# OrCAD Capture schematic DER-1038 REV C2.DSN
size D
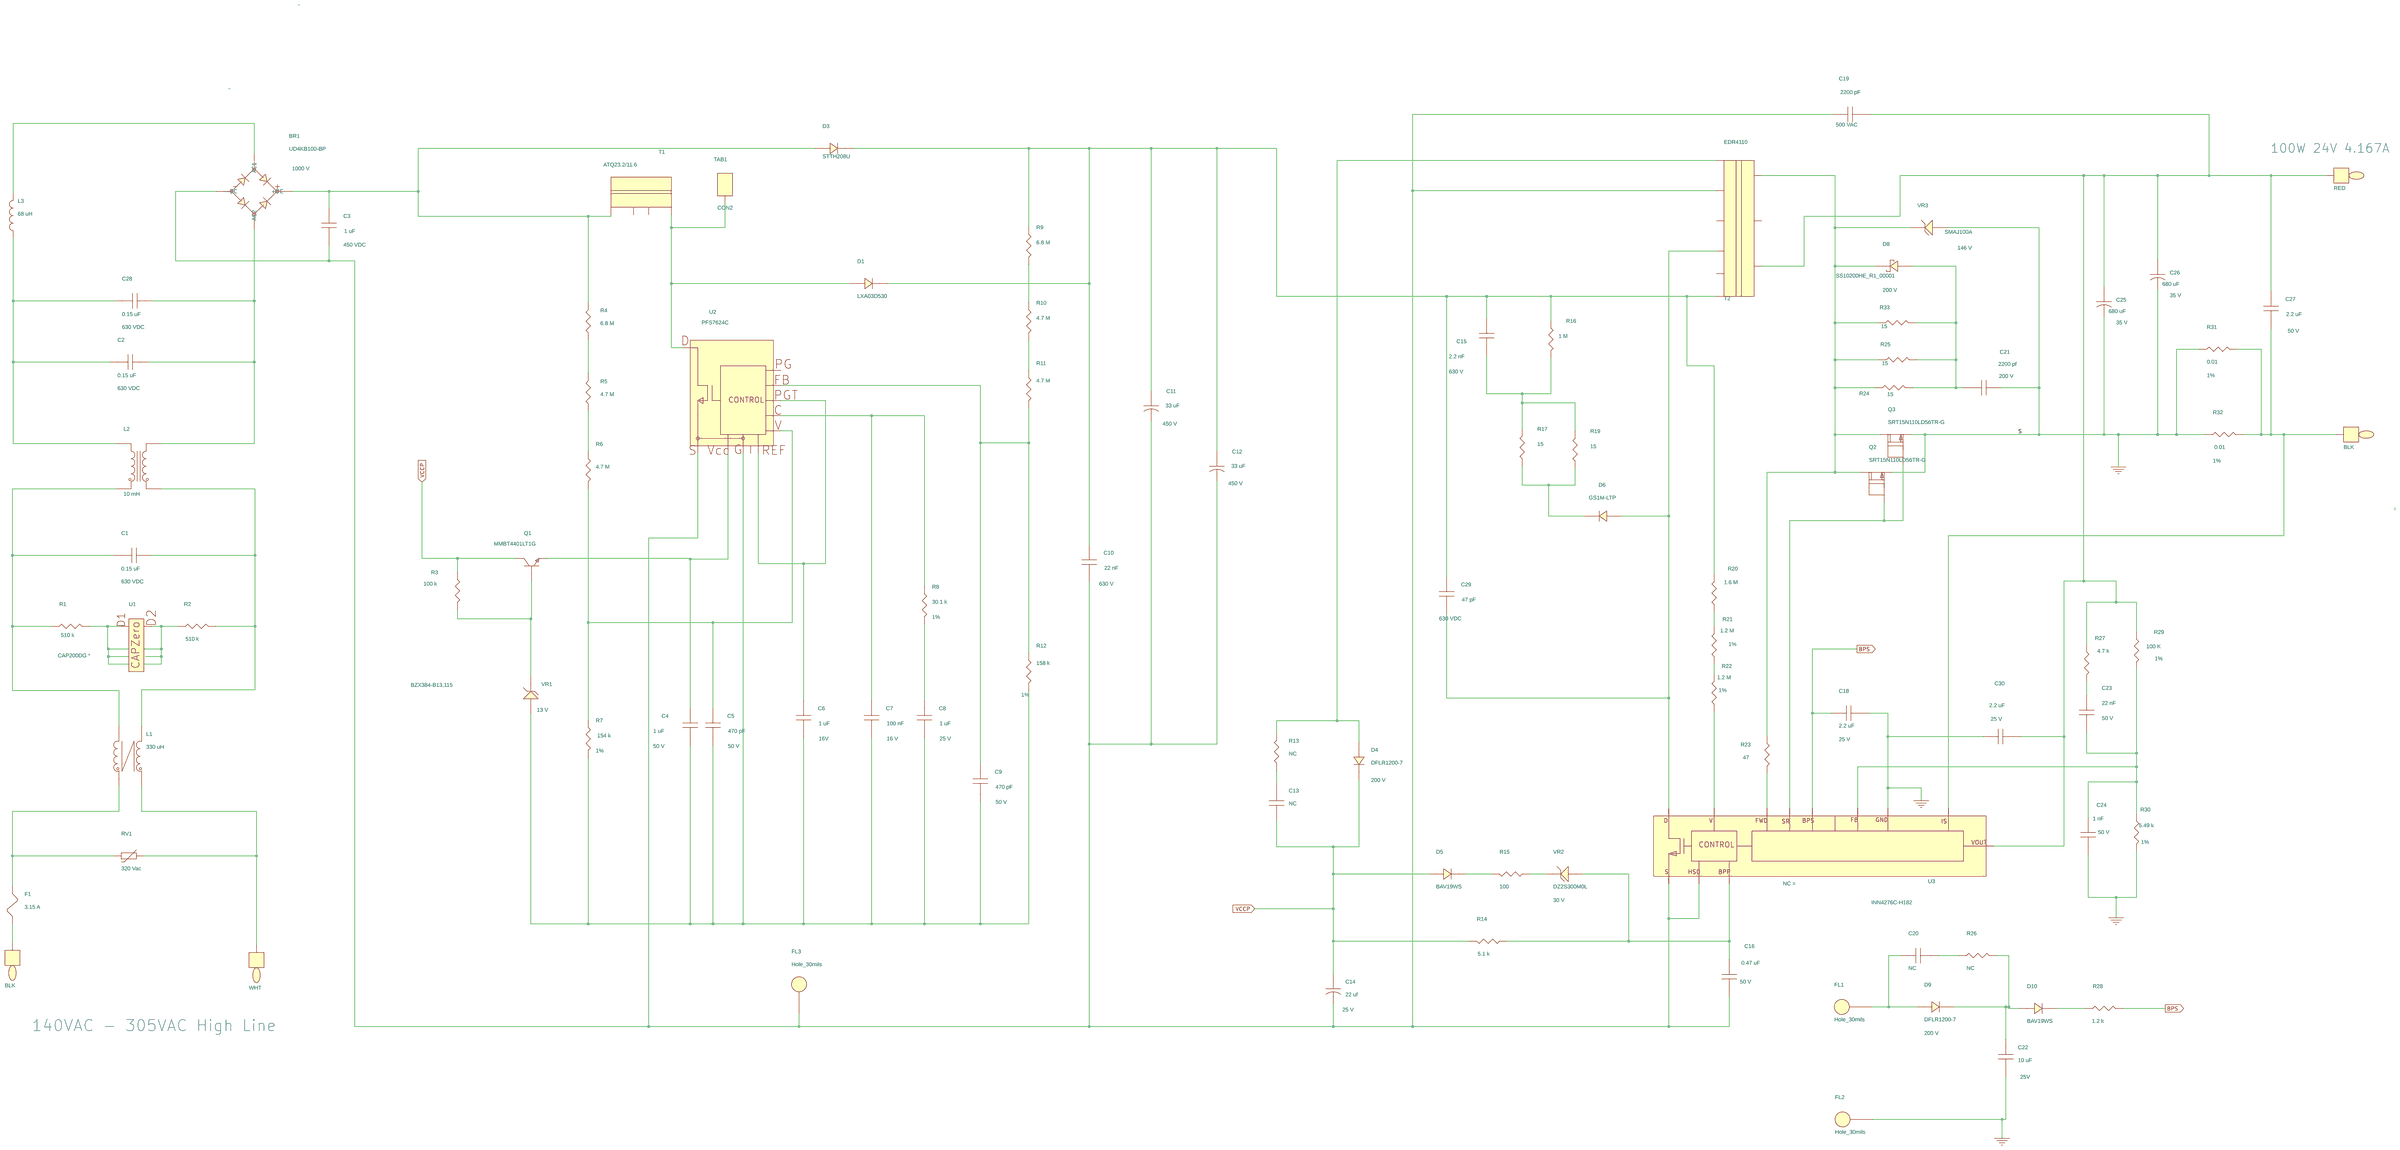
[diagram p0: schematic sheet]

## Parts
BR1  UD4KB100-BP  [pidaxbridgeD3K]
C1  0.15 uF  [pinpxcaprad13x6mm040]
C2  0.15 uF  [pinpxcaprad13x6mm040]
C3  1 uF  [pinpcaprad17p5x7p8x15mmLS]
C4  1 uF  [pismc0603]
C5  470 pF  [pismc0603]
C6  1 uF  [pismr0402]
C7  100 nF  [pismr0402]
C8  1 uF  [pismr0402]
C9  470 pF  [pismc0603]
C10  22 nF  [pismc1210]
C11  33 uF  [pipolcapd395ls200d0401705lh]
C12  33 uF  [pipolcapd395ls200d0401705lh]
C13  NC  [pismc0603]
C14  22 uf  [pi_polcap_d200_ls80_d030]
C15  2.2 nF  [pismc1206]
C16  0.47 uF  [pismc0805]
C18  2.2 uF  [pismc0805]
C19  2200 pF  [pinpcaprad11x6mmd030]
C20  NC  [pismc0603]
C21  2200 pf  [pismc0805]
C22  10 uF  [pismc0805]
C23  22 nF  [pismc0603]
C24  1 nF  [pismc0603]
C25  680 uF  [pipolcapclyd10mmD30]
C26  680 uF  [pipolcapclyd10mmD30]
C27  2.2 uF  [pismc0805]
C28  0.15 uF  [pinpxcaprad13x6mm040]
C29  47 pF  [pismc1206]
C30  2.2 uF  [pismc0805]
D1  LXA03D530  [pi_sm_diode_so8c]
D3  STTH208U  [pismdo214aa12]
D4  DFLR1200-7  [pismddflr120012]
D5  BAV19WS  [pismsod323]
D6  GS1M-LTP  [pismdo214ac12]
D8  SS10200HE_R1_00001  [pi_sm_sod-123HE]
D9  DFLR1200-7  [pismddflr120012]
D10  BAV19WS  [pismsod323]
F1  3.15 A  [pi_rst_microfuse]
FL1  Hole_30mils  [pi_hole_30mil]
FL2  Hole_30mils  [pi_hole_30mil]
FL3  Hole_30mils  [pi_hole_30mil]
L1  330 uH  [pi_toroid_CMC4p_H]
L2  10 mH  [piind4p965x571ls736x394d040]
L3  68 uH  [pi2p14Dx6mmWd060]
Q1  MMBT4401LT1G  [pismsot23123_1]
Q2  SRT15N110LD56TR-G  [pismpqfn5x6b]
Q3  SRT15N110LD56TR-G  [pismpqfn5x6b]
R1  510 k  [pismr1206]
R2  510 k  [pismr1206]
R3  100 k  [pismr0603]
R4  6.8 M  [pismr1206]
R5  4.7 M  [pismr0805]
R6  4.7 M  [pismr0805]
R7  154 k  [pismr0603]
R8  30.1 k  [pismr0402]
R9  6.8 M  [pismr1206]
R10  4.7 M  [pismr0805]
R11  4.7 M  [pismr0805]
R12  158 k  [pismr0603]
R13  NC  [pismr0603]
R14  5.1 k  [pismr0603]
R15  100  [pismr0603]
R16  1 M  [pismr1206]
R17  15  [pismr1206]
R19  15  [pismr1206]
R20  1.6 M  [pismr1206]
R21  1.2 M  [pismr0805]
R22  1.2 M  [pismr0805]
R23  47  [pismr0603]
R24  15  [pismr1206]
R25  15  [pismr1206]
R26  NC  [pismr0603]
R27  4.7 k  [pismr0603]
R28  1.2 k  [pismr0603]
R29  100 K  [pismr0603]
R30  5.49 k  [pismr0603]
R31  0.01  [pismr1206]
R32  0.01  [pismr1206]
R33  15  [pismr1206]
RV1  320 Vac  [pidisc500x225ls335x140040]
T1  ATQ23.2/11.6  [pi_bobbin_ATQ23_V_4Pb]
T2  EDR4110  [pi_bobbin_EDR4110_9p_6x3]
TAB1  CON2  [pi_conn_qc_tab_2pin_ls200]
TP1  BLK  [pitpkeystone100x100]
TP2  WHT  [pitpkeystone100x100]
TP3  RED  [pitpkeystone100x100]
TP4  BLK  [pitpkeystone100x100]
U1  CAP200DG *  [pi_ic_smd_so8_capzero]
U2  PFS7624C  [PI_IC_INSOP24B]
U3  INN4276C-H182  [pi_ic_insop_24d_IPC]
VR1  BZX384-B13,115  [pismsod323]
VR2  DZ2S300M0L  [pi_sm_d_ssmini2p]
VR3  SMAJ100A  [pismdo214ac12]

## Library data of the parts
BR1 = DISCRETE_BRIDGE_+~~-: ALT_SYMBOLS: pidaxbridgeD3K_horz; Disp_Voltage: 1000 V; FPLIST: pidaxbridgeD3K,pidaxbridgeD3K_horz; Part Number: 15-01213-00
C1 C2 C28 = CAP_NP: ALT_SYMBOLS: pinpxcaprad13x6x12Hmm040; Disp_Voltage: 630 VDC; FPLIST: pinpxcaprad13x6mm040,pinpxcaprad13x6x12Hmm040; Part Number: 20-02046-00; ROOM: 1; Voltage: 630 VDC
C3 = CAP_NP: ALT_SYMBOLS: pinpcaprad17p5x15mmLSH; Disp_Voltage: 450 VDC; FPLIST: pinpcaprad17p5x7p8x15mmLS,pinpcaprad17p5x15mmLSH; Part Number: 20-01652-00; Voltage: 450 VDC
C4 = CAP_NP: ALT_SYMBOLS: Unisem_RMCF0603UL; Disp_Voltage: 50 V; FPLIST: pismc0603,Unisem_RMCF0603UL; Part Number: 20-01555-00; ROOM: 2; Voltage: 50 V
C5 = CAP_NP: Disp_Voltage: 50 V; Part Number: 20-00510-00; ROOM: 2; Voltage: 50 V
C6 = CAP_NP: ALT_SYMBOLS: Unisem_RMCF0402UL,cc0402,pismr0402_1; Disp_Voltage: 16V; FPLIST: pismr0402,Unisem_RMCF0402UL,cc0402,pismr0402_1; Part Number: 20-01373-00; ROOM: 2; Voltage: 16V
C7 = CAP_NP: ALT_SYMBOLS: pismr0402_1; Disp_Voltage: 16 V; FPLIST: pismr0402,pismr0402_1; Part Number: 20-08759-00; ROOM: 2; Voltage: 16 V
C8 = CAP_NP: ALT_SYMBOLS: pismr0402_1; Disp_Voltage: 25 V; FPLIST: pismr0402,pismr0402_1; Part Number: 20-09151-00; ROOM: 2; Voltage: 25 V
C9 = CAP_NP: Disp_Voltage: 50 V; Part Number: 20-01167-00; ROOM: 2; Voltage: 50 V
C10 = CAP_NP: Disp_Voltage: 630 V; Part Number: 20-00732-00; Voltage: 630 V
C11 C12 = CAP_POL: Disp_Voltage: 450 V; Part Number: 20-01110-00; Voltage: 450 V
C13 C20 = CAP_NP: ALT_SYMBOLS: Unisem_RMCF0603UL; Disp_Voltage: 200 V; FPLIST: pismc0603,Unisem_RMCF0603UL; Part Number: 20-00529-00; Voltage: 200 V
C14 = CAP_POL: Disp_Voltage: 25 V; Part Number: 20-08719-00; Voltage: 25 V
C15 = CAP_NP: ALT_SYMBOLS: CAP_3216_TDK; Disp_Voltage: 630 V; FPLIST: pismc1206,CAP_3216_TDK; Part Number: 20-08609-00; ROOM: 3; Voltage: 630 V
C16 = CAP_NP: ALT_SYMBOLS: Unisem_RMCF0805UL; Disp_Voltage: 50 V; FPLIST: pismc0805,Unisem_RMCF0805UL; Part Number: 20-09197-00; ROOM: 3; Voltage: 50 V
C18 C30 = CAP_NP: Disp_Voltage: 25 V; Part Number: 20-08603-00; ROOM: 4; Voltage: 25 V
C19 = CAP_NP: Disp_Voltage: 500 VAC; Part Number: 20-01402-00; Voltage: 500 VAC
C21 = CAP_NP: ALT_SYMBOLS: Unisem_RMCF0805UL; Disp_Voltage: 200 V; FPLIST: pismc0805,Unisem_RMCF0805UL; Part Number: 20-09233-00; ROOM: 4; Voltage: 200 V
C22 = CAP_NP: ALT_SYMBOLS: Unisem_RMCF0805UL; Disp_Voltage: 25V; FPLIST: pismc0805,Unisem_RMCF0805UL; Part Number: 20-01673-00; Voltage: 25 V
C23 = CAP_NP: ALT_SYMBOLS: Unisem_RMCF0603UL; Disp_Voltage: 50 V; FPLIST: pismc0603,Unisem_RMCF0603UL; Part Number: 20-08927-00; ROOM: 4; Voltage: 50 V
C24 = CAP_NP: ALT_SYMBOLS: Unisem_RMCF0603UL; Disp_Voltage: 50 V; FPLIST: pismc0603,Unisem_RMCF0603UL; Part Number: 20-02141-00; ROOM: 4; Voltage: 50 V
C25 C26 = CAP_POL: ALT_SYMBOLS: pipolcapclyd10x18mmD30H; COMPGROUP: 3; Disp_Voltage: 35 V; FPLIST: pipolcapclyd10mmD30,pipolcapclyd10x18mmD30H; Part Number: 20-01706-00; ROOM: 4; Voltage: 35 V
C27 = CAP_NP: ALT_SYMBOLS: Unisem_RMCF0805UL; Disp_Voltage: 50 V; FPLIST: pismc0805,Unisem_RMCF0805UL; Part Number: 20-01545-00; Voltage: 50 V
C29 = CAP_NP: Disp_Voltage: 630 VDC; Part Number: 20-01456-00; Voltage: 630 VDC
D1 = DIODE_A1K8: Part Number: 15-01126-00
D3 = DIODE: Part Number: 15-00975-00; ROOM: 2
D4 D9 = DIODE: Disp_Voltage: 200 V; Part Number: 15-01019-00
D5 D10 = DIODE: Part Number: 15-00658-00
D6 = DIODE: Part Number: 15-01111-00
D8 = DIODE_SCHOTTKY: Disp_Voltage: 200 V; Part Number: 15-01774-00
F1 = FUSE: ALT_SYMBOLS: pirstmicrofusehoz; FPLIST: pi_rst_microfuse,pirstmicrofusehoz; Part Number: 40-00071-00; ROOM: 1
FL1-FL3 = FlyingLead: Part Number: 35-00284-00; ROOM: 3
L1 = TORRID_4P_12_43a: ALT_SYMBOLS: pi_toroid_CMC4p_V,pi_toroid_CMC4p_V_275uH,pi_toroid_CMC4pV275uHSF; FPLIST: pi_toroid_CMC4p_H,pi_toroid_CMC4p_V,pi_toroid_CMC4p_V_275uH,pi_toroid_CMC4pV275uHSF; Part Number: 32-00429-00
L2 = INDUCTOR_4P_1-2_4-3: Part Number: 30-00358-00
L3 = INDUCTOR: Part Number: 32-00411-00; ROOM: 1
Q1 = NPN_BEC: Part Number: 55-00152-00; ROOM: 2
Q2 Q3 = FET_N_SGD_123_4_5678: Part Number: 50-00445-00
R1 R2 = R: Part Number: 05-01417-00
R3 = R: Part Number: 05-01736-00; ROOM: 2
R4 R9 = R: Part Number: 05-01441-00; ROOM: 2
R5 R6 R10 R11 = R: ALT_SYMBOLS: Unisem_RMCF0805UL; FPLIST: pismr0805,Unisem_RMCF0805UL; Part Number: 05-01606-00; ROOM: 2
R7 = R: ALT_SYMBOLS: Unisem_RMCF0603UL; Disp_Tol: 1%; FPLIST: pismr0603,Unisem_RMCF0603UL; Part Number: 05-01192-00; ROOM: 2
R8 = R: Disp_Tol: 1%; Part Number: 05-05984-00; ROOM: 2
R12 = R: ALT_SYMBOLS: Unisem_RMCF0603UL; Disp_Tol: 1%; FPLIST: pismr0603,Unisem_RMCF0603UL; Part Number: 05-01193-00; ROOM: 2
R13 R26 = R: ALT_SYMBOLS: Unisem_RMCF0603UL; FPLIST: pismr0603,Unisem_RMCF0603UL; Part Number: 05-01675-00
R14 = R: ALT_SYMBOLS: Unisem_RMCF0603UL; FPLIST: pismr0603,Unisem_RMCF0603UL; Part Number: 05-01705-00; ROOM: 3
R15 = R: ALT_SYMBOLS: Unisem_RMCF0603UL; FPLIST: pismr0603,Unisem_RMCF0603UL; Part Number: 05-01664-00
R16 = R: Part Number: 05-01424-00
R17 R19 = R: Part Number: 05-01308-00
R20 = R: Part Number: 05-01426-00; ROOM: 3
R21 R22 = R: ALT_SYMBOLS: Unisem_RMCF0805UL; Disp_Tol: 1%; FPLIST: pismr0805,Unisem_RMCF0805UL; Part Number: 05-00878-00; ROOM: 3
R23 = R: ALT_SYMBOLS: pismr0603_1; FPLIST: pismr0603,pismr0603_1; Part Number: 05-01656-00; ROOM: 4
R24 R25 R33 = R: Part Number: 05-01308-00; ROOM: 4
R27 = R: ALT_SYMBOLS: Unisem_RMCF0603UL; FPLIST: pismr0603,Unisem_RMCF0603UL; Part Number: 05-01719-00; ROOM: 4
R28 = R: ALT_SYMBOLS: Unisem_RMCF0603UL; FPLIST: pismr0603,Unisem_RMCF0603UL; Part Number: 05-01690-00; ROOM: 4
R29 = R: Disp_Tol: 1%; Part Number: 05-06561-00; ROOM: 4
R30 = R: ALT_SYMBOLS: Unisem_RMCF0603UL; Disp_Tol: 1%; FPLIST: pismr0603,Unisem_RMCF0603UL; Part Number: 05-01149-00; ROOM: 4
R31 R32 = R: Disp_Tol: 1%; Part Number: 05-06533-00
RV1 = VARISTOR: ALT_SYMBOLS: pi_rad450x550ls300d040_h; FPLIST: pidisc500x225ls335x140040,pi_rad450x550ls300d040_h; Part Number: 85-00008-00; ROOM: 1
T1 = BATQ23.2_4P_GENERIC: Part Number: 25-01183-00
T2 = BEQ20_9P: Part Number: 25-01139-00
TAB1 = CON1_2P_TAB: Part Number: 35-00281-00
TP1 TP4 = TESTPOINT: ALT_SYMBOLS: TP_TH_CR2_D1_1; FPLIST: pitpkeystone100x100,TP_TH_CR2_D1_1; Part Number: 35-00079-00
TP2 = TESTPOINT: Part Number: 35-00081-00
TP3 = TESTPOINT: Part Number: 35-00080-00
U1 = CAPZero: Part Number: 10-00958-00
U2 = HIPERPFS-4-inSOP24B: Part Number: 10-01067-00
U3 = INNO4-QR: ALT_SYMBOLS: pi_ic_insop_24d; FPLIST: pi_ic_insop_24d_IPC, pi_ic_insop_24d; Part Number: 10-01500-00
VR1 = DIODE_ZENER: Disp_Voltage: 13 V; Part Number: 15-00819-00; ROOM: 2
VR2 = DIODE_ZENER: Disp_Voltage: 30 V; Part Number: 15-00996-00
VR3 = DIODE_ZENER: Disp_Voltage: 146 V; Part Number: 15-01987-00

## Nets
GND: C18.2 C21.1 C22.2 C24.2 C25.2 C26.2 C30.1 FL2.1 Q2.1(S) Q3.1(S) R30.2 R31.1 R32.1 U3.2 VR3.2
VCCP: C13.1 C14.1 D4.1 D5.2 Q1.3(COLLECTOR) R3.1 R14.1
BPS: C18.1 R28.2 U3.4
N13420620: C10.1 C11.1 C12.1 C15.1 C29.1 D1.8(K) D3.1 R9.1 R16.1 R20.1 T2.1
N13420648: BR1.4(-DC) C3.2 C10.2 C11.2 C12.2 C14.2 C16.2 C19.1 FL3.1 T2.5 U2.24(S) U3.15 U3.16
N13420656: C19.2 C25.1 C26.1 C27.1 C30.2 R27.1 R29.1 T2.9 TP3.1 U3.6
N13421012: C23.2 C24.1 R29.2 R30.1 U3.3
N13421042: C23.1 R27.2
N13421702: C21.2 D8.2 R24.1 R25.1 R33.1
N13421894: D8.1 Q2.5(D) Q3.5(D) R23.1 R24.2 R25.2 R33.2 T2.7 VR3.1
N13422446: Q2.4(G) Q3.4(G) U3.5
N13423706: C16.1 R14.2 U3.14 VR2.2
N13423710: C20.1 D9.2 FL1.1
N13423714: C22.1 D9.1 D10.2 R26.2
N13440082: D10.1 R28.1
N13449363: D4.2 R13.2 T2.6
N13473411: R15.1 VR2.1
N13473415: D5.1 R15.2
N13513324: C27.2 R31.2 R32.2 TP4.1 U3.1
N13515268: C13.2 R13.1
N13515819: C20.2 R26.1
N13523750: R20.2 R21.1
N13523772: R21.2 R22.1
N13523865: R22.2 U3.13
N13911889: C15.2 R16.2 R17.2 R19.2
N13911953: D6.1 R17.1 R19.1
N13912909: C29.2 D6.2 T2.3 U3.24
N13916087: R23.2 U3.7
N13925544: BR1.2(AC1) L3.2
N13925608: BR1.3(AC2) C2.1 C28.1 L2.3
N13925722: C2.2 C28.2 L2.2 L3.1
N13925782: C1.2 L1.3 L2.1 R1.1
N13925794: C1.1 L1.2 L2.4 R2.2
N13925904: R1.2 U1.1(NC1) U1.2(D1) U1.3(NC2) U1.4(NC3)
N13925908: R2.1 U1.5(NC4) U1.7(D2) U1.8(NC8)
N13925956: F1.2 L1.4 RV1.2
N13925960: L1.1 RV1.1 TP2.1
N13926028: F1.1 TP1.1
N13967468: BR1.1(+DC) C3.1 D3.2 R4.2 T1.4
N13967702: R9.2 R10.1
N13967706: R4.1 R5.2
N13967710: C9.1 R11.1 R12.2 U2.6(FB)
N13967734: C6.1 U2.3(REF) U2.8(PGT)
N13967764: C7.1 R8.1 U2.5(C)
N13967780: R5.1 R6.1
N13967788: C5.1 R6.2 R7.1 U2.4(V)
N13967796: R10.2 R11.2
N13967854: C4.1 Q1.2(EMITTER) U2.1(VCC)
N13967858: C4.2 C5.2 C6.2 C7.2 C8.2 C9.2 R7.2 R12.1 U2.2(G) VR1.2
N13968000: C8.1 R8.2
N13968020: Q1.1(BASE) R3.2 VR1.1
N13971397: D1.1(A) T1.1 TAB1.1 U2.16(D)

Not connected (* = marked no-connect by the designer): Q2 2(S2) 3(S3) 6(D6) 7(D7) 8(D8); Q3 2(S2) 3(S3) 6(D6) 7(D7) 8(D8); T1 2 3; T2 2 4 8; TAB1 2; U1 6(NC5); U2 7(PG) 12(G12)

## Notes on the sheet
- 100W 24V 4.167A
- 140VAC - 305VAC High Line
